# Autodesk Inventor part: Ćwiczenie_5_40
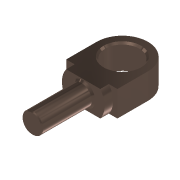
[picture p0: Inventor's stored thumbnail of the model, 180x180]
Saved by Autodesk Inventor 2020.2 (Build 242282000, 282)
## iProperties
Created: 2005-04
Part Number: Ćwiczenie_5_40
Document SubType Name: Modeling
Designer: F.Stasiak
Manufacturer: Standard
Standards Organization: Custom
Density: 1 g/cm^3
Material: Ogólny
Appearance: Brąz armatni - antyczny - polerowany
Manager: www.cadconsulting.pl
Company: Fabian Stasiak CAD Consulting
Author: F.Stasiak
Subject: Zbiór ćwiczeń. Autodesk Inventor 2020. Kurs podstawowy
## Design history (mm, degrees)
sketch "Szkic1"
  geometry: L1 (-15, 0)-(-15, -17.913); L2 (-15, -17.913)-(15, -17.913); L3 (15, -17.913)-(15, 0); A1 r 15 centre (0, 0) between (15, 0) and (-15, 0); 1 further point
  constraints: 6 end point, 2 point on circle, 2 tangent, 2 vertical, 1 centre point, 1 coincident, 1 perpendicular
  dimensions: "d0" = 30 diameter of A1
extrude "Wyciągnięcie proste1" new body sketch "Szkic1" stored distance "d1" = 15; taper "d2" = 0 deg
sketch "Szkic2"
  geometry: L1 (30, 0)-(0, 0) reference; L2 (0, -15)-(30, -15) reference; L3 (0, 0)-(30, -15); A1 r 12.5 centre (15, -7.5) between (5, 0) and (5, -15); A2 r 12.5 centre (15, -7.5) between (25, -15) and (25, 0)
  constraints: 4 point on circle, 4 point on line, 2 centre point, 2 end point, 1 midpoint
extrude "Wyciągnięcie proste2" join sketch "Szkic2" distance "d4" = 5; taper "d5" = 0 deg
sketch "Szkic3"
  geometry: C1 r 6 at (15, -7.5); A1 r 12.5 centre (15, -7.5) between (5, 0) and (5, -15) reference
  constraints: 1 centre point, 1 coincident
  dimensions: "d6" = 12 diameter of C1
extrude "Wyciągnięcie proste3" join sketch "Szkic3" distance "d7" = 30; taper "d8" = 0 deg
chamfer "Faza1" distance "d9" = 0.5; stored, may be unused: second distance "d10" = 2, angle "d11" = 45 deg
sketch "Szkic4"
  geometry: C1 r 10 at (0, 0); A1 r 15 centre (0, 0) between (15, 0) and (-15, 0) reference
  constraints: 1 centre point, 1 coincident
  dimensions: "d12" = 20 diameter of C1
extrude "Wyciągnięcie proste4" cut sketch "Szkic4" extent not by distance; stored distance "d13" = 30; taper "d14" = 0 deg
chamfer "Faza3" distance "d18" = 1; stored, may be unused: second distance "d19" = 2, angle "d20" = 45 deg
chamfer "Faza4" distance "d25" = 1; stored, may be unused: second distance "d26" = 2, angle "d27" = 45 deg
node "Bryła1"
node "Korpusy bryłowe"
node "Korpusy powierzchniowe"
other parameters: "d3" = 25
